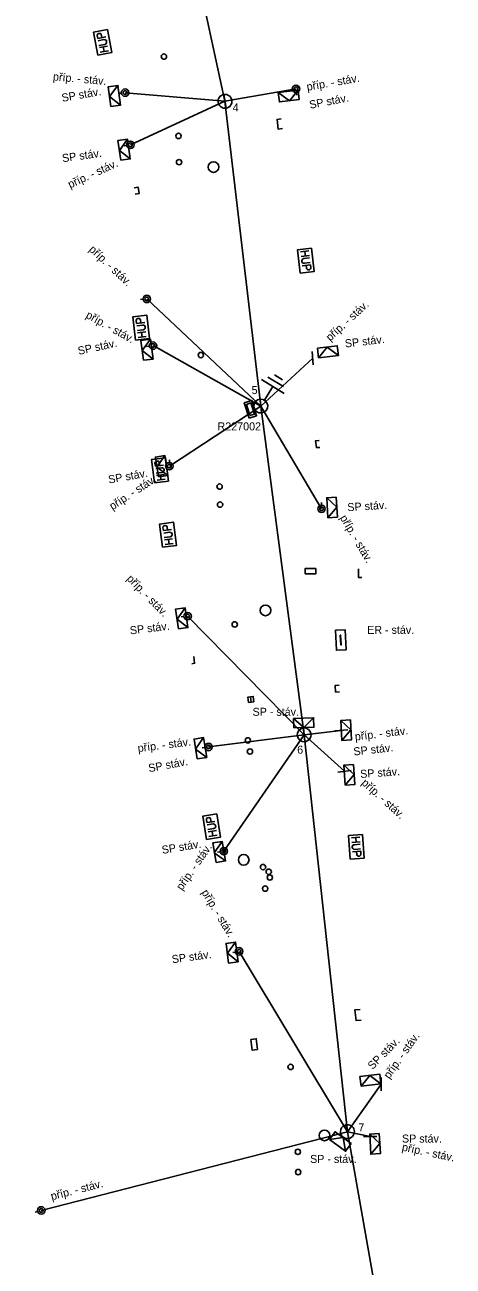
# Model space of a CAD drawing. Extents: x -577028 to -568584, y -1207664 to -1202947.
# Drawn here: x -573450.8 to -573410.7, y -1206512.4 to -1206396.1 of the extents above; entities that cross this region are included whole.
import ezdxf

# ---------------------------------------------------------------- set-up
doc = ezdxf.new("R2010")
doc.units = 0
for name, color, linetype in [('CIZÍ_NADZEM', 7, 'Continuous'), ('ELE_EON', 7, 'Continuous'), ('ELE_EON_POPIS', 7, 'Continuous')]:
    doc.layers.add(name, color=color, linetype=linetype)

msp = doc.modelspace()

# ---------------------------------------------------------------- linework, layer by layer
at = {"layer": 'CIZÍ_NADZEM'}
msp.add_line((-573429.64, -1206459.54), (-573429.7, -1206459.04), dxfattribs=at)
for points in [[(-573444.01, -1206398.9), (-573444.41, -1206396.74), (-573443.11, -1206396.5), (-573442.71, -1206398.66), (-573444.01, -1206398.9)], [(-573444.02, -1206397.34), (-573444.07, -1206397.06), (-573444.05, -1206396.96), (-573444.02, -1206396.92), (-573443.95, -1206396.88), (-573443.85, -1206396.86), (-573443.77, -1206396.87), (-573443.73, -1206396.9), (-573443.68, -1206396.98), (-573443.62, -1206397.26)], [(-573443.26, -1206397.2), (-573444.02, -1206397.34)], [(-573443.9, -1206397.99), (-573443.35, -1206397.89), (-573443.25, -1206397.84), (-573443.19, -1206397.76), (-573443.18, -1206397.66), (-573443.19, -1206397.6), (-573443.24, -1206397.51), (-573443.32, -1206397.46), (-573443.44, -1206397.45), (-573443.98, -1206397.55)], [(-573443.1, -1206398.06), (-573443.86, -1206398.2)], [(-573443.42, -1206398.57), (-573443.5, -1206398.13)], [(-573443.78, -1206398.63), (-573443.02, -1206398.5)], [(-573426.83, -1206404.88), (-573427.22, -1206404.93), (-573427.12, -1206405.84), (-573426.71, -1206405.79)], [(-573440.5, -1206411.92), (-573440.13, -1206411.86), (-573440.23, -1206411.28), (-573440.59, -1206411.34)], [(-573424.01, -1206416.99), (-573423.75, -1206419.18), (-573425.06, -1206419.33), (-573425.32, -1206417.15), (-573424.01, -1206416.99)], [(-573424.25, -1206417.25), (-573425.02, -1206417.33)], [(-573424.97, -1206417.77), (-573424.2, -1206417.68)], [(-573424.18, -1206417.9), (-573424.73, -1206417.96), (-573424.83, -1206418.01), (-573424.89, -1206418.08), (-573424.92, -1206418.18), (-573424.91, -1206418.24), (-573424.87, -1206418.33), (-573424.79, -1206418.39), (-573424.67, -1206418.4), (-573424.13, -1206418.34)], [(-573424.61, -1206417.29), (-573424.56, -1206417.73)], [(-573424.87, -1206418.65), (-573424.1, -1206418.56)], [(-573424.1, -1206418.56), (-573424.07, -1206418.84), (-573424.09, -1206418.94), (-573424.13, -1206418.97), (-573424.19, -1206419.01), (-573424.3, -1206419.02), (-573424.38, -1206419), (-573424.42, -1206418.97), (-573424.47, -1206418.89), (-573424.5, -1206418.6)], [(-573440.48, -1206425.61), (-573440.72, -1206423.42), (-573439.41, -1206423.28), (-573439.17, -1206425.46), (-573440.48, -1206425.61)], [(-573440.38, -1206424.05), (-573440.41, -1206423.76), (-573440.38, -1206423.67), (-573440.35, -1206423.63), (-573440.28, -1206423.59), (-573440.17, -1206423.58), (-573440.1, -1206423.6), (-573440.06, -1206423.63), (-573440.01, -1206423.72), (-573439.98, -1206424)], [(-573439.61, -1206423.96), (-573440.38, -1206424.05)], [(-573440.3, -1206424.7), (-573439.76, -1206424.64), (-573439.65, -1206424.6), (-573439.59, -1206424.52), (-573439.56, -1206424.43), (-573439.57, -1206424.37), (-573439.61, -1206424.28), (-573439.69, -1206424.22), (-573439.8, -1206424.2), (-573440.35, -1206424.26)], [(-573439.52, -1206424.84), (-573440.28, -1206424.92)], [(-573439.87, -1206425.32), (-573439.92, -1206424.88)], [(-573440.23, -1206425.36), (-573439.47, -1206425.27)], [(-573423.27, -1206435.01), (-573423.62, -1206435.04), (-573423.54, -1206435.69), (-573423.22, -1206435.66)], [(-573438.7, -1206438.99), (-573438.98, -1206436.8), (-573437.67, -1206436.64), (-573437.39, -1206438.82), (-573438.7, -1206438.99)], [(-573438.62, -1206437.42), (-573438.66, -1206437.14), (-573438.63, -1206437.04), (-573438.6, -1206437.01), (-573438.53, -1206436.97), (-573438.42, -1206436.95), (-573438.35, -1206436.97), (-573438.31, -1206437), (-573438.26, -1206437.09), (-573438.22, -1206437.37)], [(-573437.86, -1206437.33), (-573438.62, -1206437.42)], [(-573438.54, -1206438.08), (-573437.99, -1206438.01), (-573437.89, -1206437.97), (-573437.82, -1206437.89), (-573437.8, -1206437.79), (-573437.81, -1206437.73), (-573437.86, -1206437.64), (-573437.94, -1206437.59), (-573438.05, -1206437.57), (-573438.59, -1206437.64)], [(-573437.75, -1206438.2), (-573438.51, -1206438.29)], [(-573438.46, -1206438.73), (-573437.69, -1206438.64)], [(-573438.1, -1206438.69), (-573438.15, -1206438.25)], [(-573437.95, -1206445.03), (-573438.23, -1206442.85), (-573436.92, -1206442.68), (-573436.64, -1206444.86), (-573437.95, -1206445.03)], [(-573437.87, -1206443.47), (-573437.91, -1206443.19), (-573437.89, -1206443.09), (-573437.85, -1206443.05), (-573437.79, -1206443.01), (-573437.68, -1206443), (-573437.6, -1206443.02), (-573437.56, -1206443.05), (-573437.51, -1206443.13), (-573437.48, -1206443.42)], [(-573437.11, -1206443.37), (-573437.87, -1206443.47)], [(-573437.79, -1206444.12), (-573437.24, -1206444.05), (-573437.14, -1206444.01), (-573437.07, -1206443.93), (-573437.05, -1206443.83), (-573437.06, -1206443.77), (-573437.11, -1206443.68), (-573437.19, -1206443.63), (-573437.3, -1206443.61), (-573437.84, -1206443.69)], [(-573437, -1206444.24), (-573437.76, -1206444.34)], [(-573437.7, -1206444.78), (-573436.94, -1206444.68)], [(-573437.34, -1206444.73), (-573437.4, -1206444.29)], [(-573419.61, -1206447.05), (-573419.59, -1206447.87), (-573419.28, -1206447.86)], [(-573435.22, -1206455.94), (-573434.94, -1206455.89), (-573435.02, -1206455.25)], [(-573421.39, -1206458.58), (-573421.74, -1206458.6), (-573421.78, -1206457.98), (-573421.42, -1206457.96)], [(-573433.84, -1206472.4), (-573434.17, -1206470.22), (-573432.87, -1206470.02), (-573432.53, -1206472.2), (-573433.84, -1206472.4)], [(-573433.8, -1206470.83), (-573433.84, -1206470.55), (-573433.82, -1206470.45), (-573433.79, -1206470.41), (-573433.72, -1206470.37), (-573433.61, -1206470.36), (-573433.54, -1206470.38), (-573433.5, -1206470.4), (-573433.45, -1206470.49), (-573433.4, -1206470.77)], [(-573433.04, -1206470.72), (-573433.8, -1206470.83)], [(-573433.7, -1206471.48), (-573433.15, -1206471.4), (-573433.05, -1206471.35), (-573432.99, -1206471.28), (-573432.97, -1206471.18), (-573432.98, -1206471.12), (-573433.03, -1206471.03), (-573433.11, -1206470.98), (-573433.22, -1206470.96), (-573433.77, -1206471.05)], [(-573432.91, -1206471.58), (-573433.67, -1206471.7)], [(-573433.24, -1206472.08), (-573433.31, -1206471.65)], [(-573433.6, -1206472.14), (-573432.84, -1206472.02)], [(-573419.22, -1206471.96), (-573419.07, -1206474.15), (-573420.38, -1206474.25), (-573420.54, -1206472.05), (-573419.22, -1206471.96)], [(-573419.48, -1206472.2), (-573420.25, -1206472.25)], [(-573420.22, -1206472.69), (-573419.45, -1206472.64)], [(-573419.43, -1206472.86), (-573419.98, -1206472.9), (-573420.09, -1206472.93), (-573420.16, -1206473.01), (-573420.19, -1206473.1), (-573420.18, -1206473.17), (-573420.14, -1206473.26), (-573420.06, -1206473.31), (-573419.95, -1206473.34), (-573419.4, -1206473.3)], [(-573419.84, -1206472.22), (-573419.81, -1206472.67)], [(-573420.15, -1206473.57), (-573419.39, -1206473.52)], [(-573419.39, -1206473.52), (-573419.37, -1206473.8), (-573419.4, -1206473.9), (-573419.43, -1206473.93), (-573419.5, -1206473.97), (-573419.61, -1206473.97), (-573419.69, -1206473.95), (-573419.72, -1206473.92), (-573419.77, -1206473.83), (-573419.79, -1206473.54)], [(-573419.44, -1206488.34), (-573419.95, -1206488.38), (-573419.83, -1206489.38), (-573419.36, -1206489.35)]]:
    msp.add_lwpolyline(points, dxfattribs=at)
for points in [[(-573424.6, -1206447.52), (-573423.6, -1206447.52), (-573423.6, -1206447.02), (-573424.6, -1206447.02)], [(-573429.39, -1206459.51), (-573429.45, -1206459.01), (-573429.95, -1206459.07), (-573429.89, -1206459.57)], [(-573429.68, -1206491.15), (-573429.56, -1206492.15), (-573429.06, -1206492.09), (-573429.18, -1206491.09)]]:
    msp.add_lwpolyline(points, close=True, dxfattribs=at)
for centre, radius in [((-573437.82, -1206399.04), 0.25), ((-573436.45, -1206406.48), 0.25), ((-573436.4, -1206408.93), 0.25), ((-573433.18, -1206409.39), 0.5), ((-573434.36, -1206427.01), 0.25), ((-573432.6, -1206439.34), 0.25), ((-573432.56, -1206441.03), 0.25), ((-573428.31, -1206450.94), 0.5), ((-573431.19, -1206452.26), 0.25), ((-573429.96, -1206463.13), 0.25), ((-573429.76, -1206464.17), 0.25), ((-573430.35, -1206474.32), 0.5), ((-573428.54, -1206475), 0.25), ((-573428.01, -1206475.44), 0.25), ((-573427.9, -1206475.98), 0.25), ((-573428.34, -1206477.02), 0.25), ((-573425.96, -1206493.73), 0.25), ((-573422.78, -1206500.15), 0.5), ((-573425.28, -1206501.69), 0.25), ((-573425.25, -1206503.59), 0.25)]:
    msp.add_circle(centre, radius, dxfattribs=at)
at = {"layer": 'ELE_EON'}
for p, q in [((-573441.81, -1206402.48), (-573442.05, -1206402.52)), ((-573432, -1206403.87), (-573432.2, -1206402.59)), ((-573425.41, -1206402.41), (-573425.38, -1206402.66)), ((-573441.31, -1206407.37), (-573441.55, -1206407.41)), ((-573439.77, -1206421.78), (-573440.02, -1206421.8)), ((-573439.19, -1206426.17), (-573439.44, -1206426.21)), ((-573423.83, -1206427.93), (-573423.95, -1206426.69)), ((-573426.55, -1206430.61), (-573428.68, -1206429.3)), ((-573426.63, -1206429.97), (-573428.08, -1206429.09)), ((-573426.71, -1206429.34), (-573427.48, -1206428.87)), ((-573427.62, -1206429.96), (-573428.4, -1206431.24)), ((-573428.68, -1206432.44), (-573428.8, -1206431.14)), ((-573437.31, -1206437.07), (-573437.31, -1206436.82)), ((-573423.06, -1206441.07), (-573423.06, -1206440.82)), ((-573435.95, -1206451.52), (-573436.2, -1206451.55)), ((-573424.62, -1206463.26), (-573424.76, -1206461.96)), ((-573420.59, -1206462.14), (-573421.83, -1206462.24)), ((-573433.99, -1206463.79), (-573434.23, -1206463.83)), ((-573420.29, -1206465.95), (-573421.53, -1206466.09)), ((-573432.56, -1206473.56), (-573432.8, -1206473.59)), ((-573431.12, -1206482.97), (-573431.37, -1206483.02)), ((-573417.48, -1206495.97), (-573417.48, -1206494.72)), ((-573420.5, -1206500.43), (-573420.78, -1206499.17)), ((-573417.89, -1206500.25), (-573419.14, -1206500.25)), ((-573449.64, -1206507.27), (-573449.88, -1206507.33))]:
    msp.add_line(p, q, dxfattribs=at)
for points in [[(-573417.05, -1206561.72), (-573414.28, -1206535.75), (-573420.64, -1206499.8), (-573424.69, -1206462.61), (-573428.74, -1206431.79), (-573432.1, -1206403.23), (-573438.62, -1206373.19), (-573445.84, -1206342.55), (-573450.84, -1206308.78)], [(-573441.89, -1206403.6), (-573442.9, -1206402.79), (-573442.13, -1206401.74)], [(-573441.46, -1206402.42), (-573432.1, -1206403.23)], [(-573432.1, -1206403.23), (-573425.45, -1206402.06)], [(-573425.25, -1206402.17), (-573426.07, -1206403.17), (-573427.11, -1206402.39)], [(-573440.96, -1206407.31), (-573432.1, -1206403.23)], [(-573440.97, -1206408.63), (-573441.99, -1206407.83), (-573441.23, -1206406.77)], [(-573439.42, -1206421.75), (-573428.74, -1206431.79)], [(-573438.84, -1206427.39), (-573439.85, -1206426.57), (-573439.08, -1206425.53)], [(-573438.84, -1206426.13), (-573428.74, -1206431.79)], [(-573423.34, -1206427.26), (-573422.52, -1206426.26), (-573421.48, -1206427.04)], [(-573428.74, -1206431.79), (-573423.89, -1206427.31)], [(-573428.74, -1206431.79), (-573437.31, -1206437.42)], [(-573428.74, -1206431.79), (-573423.06, -1206441.42)], [(-573437.45, -1206438.3), (-573438.48, -1206437.51), (-573437.73, -1206436.44)], [(-573422.58, -1206440.38), (-573421.62, -1206441.27), (-573422.46, -1206442.26)], [(-573435.57, -1206452.55), (-573436.59, -1206451.75), (-573435.83, -1206450.69)], [(-573435.6, -1206451.48), (-573424.69, -1206462.61)], [(-573425.68, -1206461.06), (-573424.71, -1206461.93), (-573423.81, -1206461)], [(-573421.25, -1206461.25), (-573420.31, -1206462.15), (-573421.17, -1206463.13)], [(-573424.69, -1206462.61), (-573421.21, -1206462.19)], [(-573433.81, -1206464.72), (-573434.85, -1206463.94), (-573434.11, -1206462.86)], [(-573433.64, -1206463.74), (-573424.69, -1206462.61)], [(-573432.21, -1206473.51), (-573424.69, -1206462.61)], [(-573424.69, -1206462.61), (-573420.91, -1206466.02)], [(-573420.96, -1206465.44), (-573420, -1206466.32), (-573420.84, -1206467.32)], [(-573432.05, -1206474.43), (-573433.1, -1206473.66), (-573432.37, -1206472.59)], [(-573430.87, -1206483.89), (-573431.88, -1206483.08), (-573431.11, -1206482.03)], [(-573420.64, -1206499.8), (-573430.78, -1206482.9)], [(-573419.36, -1206495.52), (-573418.53, -1206494.53), (-573417.5, -1206495.32)], [(-573420.64, -1206499.8), (-573417.48, -1206495.34)], [(-573420.64, -1206499.8), (-573449.3, -1206507.18)], [(-573420.81, -1206501.63), (-573421.04, -1206500.35), (-573422.33, -1206500.53)], [(-573420.64, -1206499.8), (-573418.51, -1206500.25)], [(-573418.55, -1206500.03), (-573417.6, -1206500.92), (-573418.45, -1206501.91)]]:
    msp.add_lwpolyline(points, dxfattribs=at)
for points in [[(-573442.78, -1206403.72), (-573443.03, -1206401.86), (-573442.13, -1206401.74), (-573441.89, -1206403.6)], [(-573425.14, -1206403.06), (-573427, -1206403.29), (-573427.11, -1206402.39), (-573425.25, -1206402.17)], [(-573441.86, -1206408.76), (-573442.12, -1206406.9), (-573441.23, -1206406.77), (-573440.97, -1206408.63)], [(-573439.73, -1206427.5), (-573439.97, -1206425.64), (-573439.08, -1206425.53), (-573438.84, -1206427.39)], [(-573423.45, -1206426.37), (-573421.59, -1206426.14), (-573421.48, -1206427.04), (-573423.34, -1206427.26)], [(-573429.85, -1206432.92), (-573430.3, -1206431.49), (-573429.58, -1206431.27), (-573429.14, -1206432.7)], [(-573429.77, -1206432.69), (-573430.1, -1206431.64), (-573429.67, -1206431.5), (-573429.34, -1206432.55)], [(-573438.34, -1206438.43), (-573438.62, -1206436.58), (-573437.73, -1206436.44), (-573437.45, -1206438.3)], [(-573421.68, -1206440.33), (-573421.57, -1206442.2), (-573422.46, -1206442.26), (-573422.58, -1206440.38)], [(-573436.46, -1206452.67), (-573436.72, -1206450.82), (-573435.83, -1206450.69), (-573435.57, -1206452.55)], [(-573421.76, -1206452.8), (-573421.66, -1206454.68), (-573420.76, -1206454.63), (-573420.86, -1206452.75)], [(-573421.31, -1206453.25), (-573421.25, -1206454.18), (-573421.22, -1206454.18), (-573421.27, -1206453.25)], [(-573425.65, -1206461.96), (-573423.78, -1206461.9), (-573423.81, -1206461), (-573425.68, -1206461.06)], [(-573420.36, -1206461.21), (-573420.27, -1206463.08), (-573421.17, -1206463.13), (-573421.25, -1206461.25)], [(-573434.7, -1206464.86), (-573435, -1206463.01), (-573434.11, -1206462.86), (-573433.81, -1206464.72)], [(-573420.07, -1206465.38), (-573419.94, -1206467.25), (-573420.84, -1206467.32), (-573420.96, -1206465.44)], [(-573432.94, -1206474.58), (-573433.25, -1206472.73), (-573432.37, -1206472.59), (-573432.05, -1206474.43)], [(-573431.76, -1206484.01), (-573432, -1206482.15), (-573431.11, -1206482.03), (-573430.87, -1206483.89)], [(-573419.46, -1206494.63), (-573417.59, -1206494.42), (-573417.5, -1206495.32), (-573419.36, -1206495.52)], [(-573420.28, -1206500.9), (-573421.8, -1206499.8), (-573422.33, -1206500.53), (-573420.81, -1206501.63)], [(-573417.65, -1206499.98), (-573417.55, -1206501.86), (-573418.45, -1206501.91), (-573418.55, -1206500.03)]]:
    msp.add_lwpolyline(points, close=True, dxfattribs=at)
for centre, radius in [((-573425.45, -1206402.06), 0.35), ((-573425.45, -1206402.06), 0.175), ((-573441.46, -1206402.42), 0.35), ((-573441.46, -1206402.42), 0.175), ((-573440.96, -1206407.31), 0.35), ((-573440.96, -1206407.31), 0.175), ((-573439.42, -1206421.75), 0.35), ((-573439.42, -1206421.75), 0.175), ((-573438.84, -1206426.13), 0.35), ((-573438.84, -1206426.13), 0.175), ((-573437.31, -1206437.42), 0.35), ((-573437.31, -1206437.42), 0.175), ((-573423.06, -1206441.42), 0.35), ((-573423.06, -1206441.42), 0.175), ((-573435.6, -1206451.48), 0.35), ((-573435.6, -1206451.48), 0.175), ((-573433.64, -1206463.74), 0.35), ((-573433.64, -1206463.74), 0.175), ((-573432.21, -1206473.51), 0.35), ((-573432.21, -1206473.51), 0.175), ((-573430.78, -1206482.9), 0.35), ((-573430.78, -1206482.9), 0.175), ((-573449.3, -1206507.18), 0.35), ((-573449.3, -1206507.18), 0.175)]:
    msp.add_circle(centre, radius, dxfattribs=at)
for centre, start, end in [((-573432.1, -1206403.23), 98.4432, 278.4432), ((-573432.1, -1206403.23), 278.4432, 98.4432), ((-573428.74, -1206431.79), 95.6673, 275.6673), ((-573428.74, -1206431.79), 275.6673, 95.6673), ((-573424.69, -1206462.61), 95.856, 275.856), ((-573424.69, -1206462.61), 275.856, 95.856), ((-573420.64, -1206499.8), 102.6526, 282.6526), ((-573420.64, -1206499.8), 282.6526, 102.6526)]:
    msp.add_arc(centre, 0.65, start, end, dxfattribs=at)

# ---------------------------------------------------------------- texts
at = {"layer": 'ELE_EON_POPIS'}
for s, rotation, p in [('příp. - stáv.', 355.054, (-573448.23, -1206401.27)), ('příp. - stáv.', 9.9785, (-573424.39, -1206402.25)), ('SP stáv.', 9.7824, (-573447.33, -1206403.28)), ('SP stáv.', 10.6998, (-573424.13, -1206403.93)), ('SP stáv.', 7.8947, (-573447.3, -1206408.94)), ('příp. - stáv.', 24.7259, (-573446.6, -1206411.4)), ('příp. - stáv.', 316.7692, (-573444.89, -1206417.19)), ('příp. - stáv.', 42.729, (-573422.25, -1206425.76)), ('příp. - stáv.', 330.7339, (-573445.2, -1206423.48)), ('SP stáv.', 6.6929, (-573420.83, -1206426.31)), ('SP stáv.', 12.1957, (-573445.79, -1206427)), ('SP stáv.', 10.091, (-573442.96, -1206439.06)), ('příp. - stáv.', 33.3026, (-573442.63, -1206441.57)), ('SP stáv.', 3.4799, (-573420.62, -1206441.65)), ('příp. - stáv.', 300.5331, (-573421.37, -1206442.26)), ('příp. - stáv.', 314.4281, (-573441.36, -1206448.03)), ('SP stáv.', 6.9272, (-573440.96, -1206453.2)), ('příp. - stáv.', 6.8817, (-573419.9, -1206463.15)), ('příp. - stáv.', 7.1959, (-573440.23, -1206464.23)), ('SP stáv.', 6.2484, (-573420.03, -1206464.55)), ('SP stáv.', 10.3366, (-573439.2, -1206466.11)), ('SP stáv.', 3.9195, (-573419.42, -1206466.65)), ('příp. - stáv.', 317.9459, (-573419.38, -1206467.19)), ('SP stáv.', 9.1967, (-573437.96, -1206473.77)), ('příp. - stáv.', 55.3979, (-573436.12, -1206477.24)), ('příp. - stáv.', 300.9637, (-573434.33, -1206477.37)), ('SP stáv.', 7.6705, (-573437.03, -1206484.02)), ('SP stáv.', 45.4286, (-573418.29, -1206494.03)), ('příp. - stáv.', 54.6817, (-573416.72, -1206494.9)), ('příp. - stáv.', 348.0707, (-573415.58, -1206501.57)), ('příp. - stáv.', 14.4401, (-573448.31, -1206506.23))]:
    msp.add_text(s, height=0.75, rotation=rotation, dxfattribs=at).set_placement(p)
for s, p in [('4', (-573431.38, -1206404.18)), ('5', (-573429.61, -1206430.67)), ('R227002', (-573432.8, -1206434.07)), ('ER - stáv.', (-573418.79, -1206453.14)), ('SP - stáv.', (-573429.52, -1206460.82)), ('6', (-573425.34, -1206464.37)), ('7', (-573419.61, -1206499.77)), ('SP stáv.', (-573415.53, -1206500.82)), ('SP - stáv.', (-573424.13, -1206502.73))]:
    msp.add_text(s, height=0.75, dxfattribs=at).set_placement(p)

doc.saveas('drawing.dxf')
